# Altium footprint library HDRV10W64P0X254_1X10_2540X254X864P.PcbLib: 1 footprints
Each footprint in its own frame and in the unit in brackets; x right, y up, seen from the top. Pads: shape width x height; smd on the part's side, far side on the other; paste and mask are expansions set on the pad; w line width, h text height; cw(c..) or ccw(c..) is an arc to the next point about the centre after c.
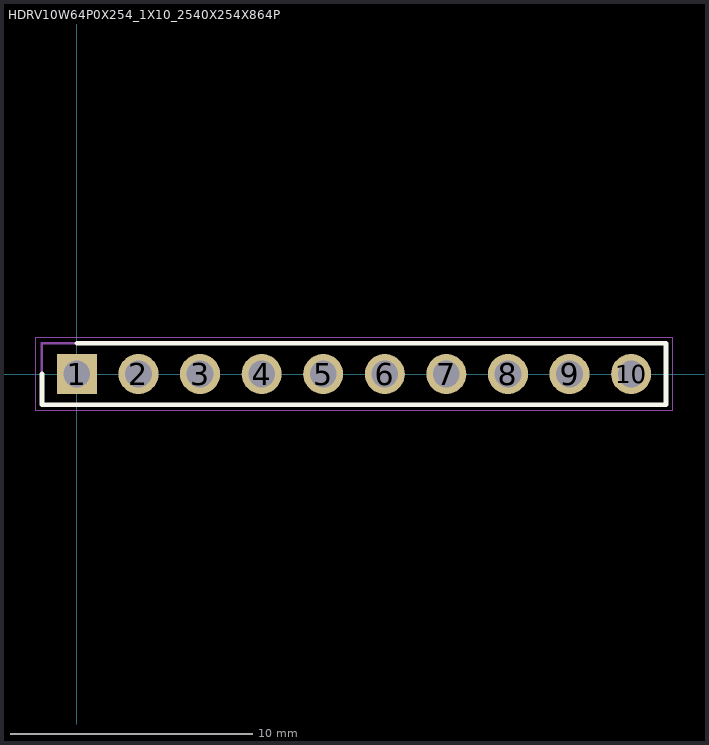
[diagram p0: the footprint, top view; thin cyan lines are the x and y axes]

## HDRV10W64P0X254_1X10_2540X254X864P [mm]
pads (10):
  rect 1.65x1.65 / inner round 1.65 / far side rect 1.65x1.65 hole 1.1: 1(0,0)
  round 1.65 hole 1.1: 2(2.54,0) 3(5.08,0) 4(7.62,0) 5(10.16,0) 6(12.7,0) 7(15.24,0) 8(17.78,0) 9(20.32,0) 10(22.86,0)
Top Overlay:
  lines w0.2: -1.445,0 -1.445,-1.27 24.305,-1.27 24.305,1.27 0,1.27
Mechanical 15:
  lines w0.1: -1.445,-1.27 24.305,-1.27 24.305,1.27 -1.445,1.27 -1.445,-1.27
Mechanical 20:
  lines w0.05: -1.695,-1.52 24.555,-1.52 24.555,1.52 -1.695,1.52 -1.695,-1.52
